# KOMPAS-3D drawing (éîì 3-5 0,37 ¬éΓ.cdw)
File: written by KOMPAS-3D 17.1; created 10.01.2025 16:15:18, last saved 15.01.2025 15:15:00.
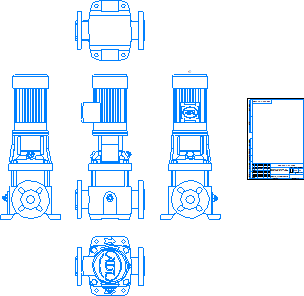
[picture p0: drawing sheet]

Sheet 1: A4, portrait

Title block, sheet 1: name: ВМН 3-5 0,37 кВт; designation: ВМН 3-5 0,37 кВт; material: Сталь 10  ГОСТ 1050-2013; mass: 66,74; sheets: 1; sheet format: A4; stored path: \\adlc.lan\data\АДЛ_ПКД\3D-модели\ADL production\Насосы ГРАНПАМП\Насосы ВМН\ВМН3\KOMPAS 3D\3-5 0,37 кВт _ ВМН.cdw

Views: Проекционный вид 2, Проекционный вид 3, Проекционный вид 4, Проекционный вид 5
Referenced files in \\adlc.lan\data\АДЛ_ПКД\3D-модели\ADL production\Насосы ГРАНПАМП\Насосы ВМН\ВМН3\KOMPAS 3D\: ВМН 3-5 0,37 кВт.m3d
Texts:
  Andrey
  АДЛ
Dimensions and other numbers on the sheet: 1:1; 1; 66,74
